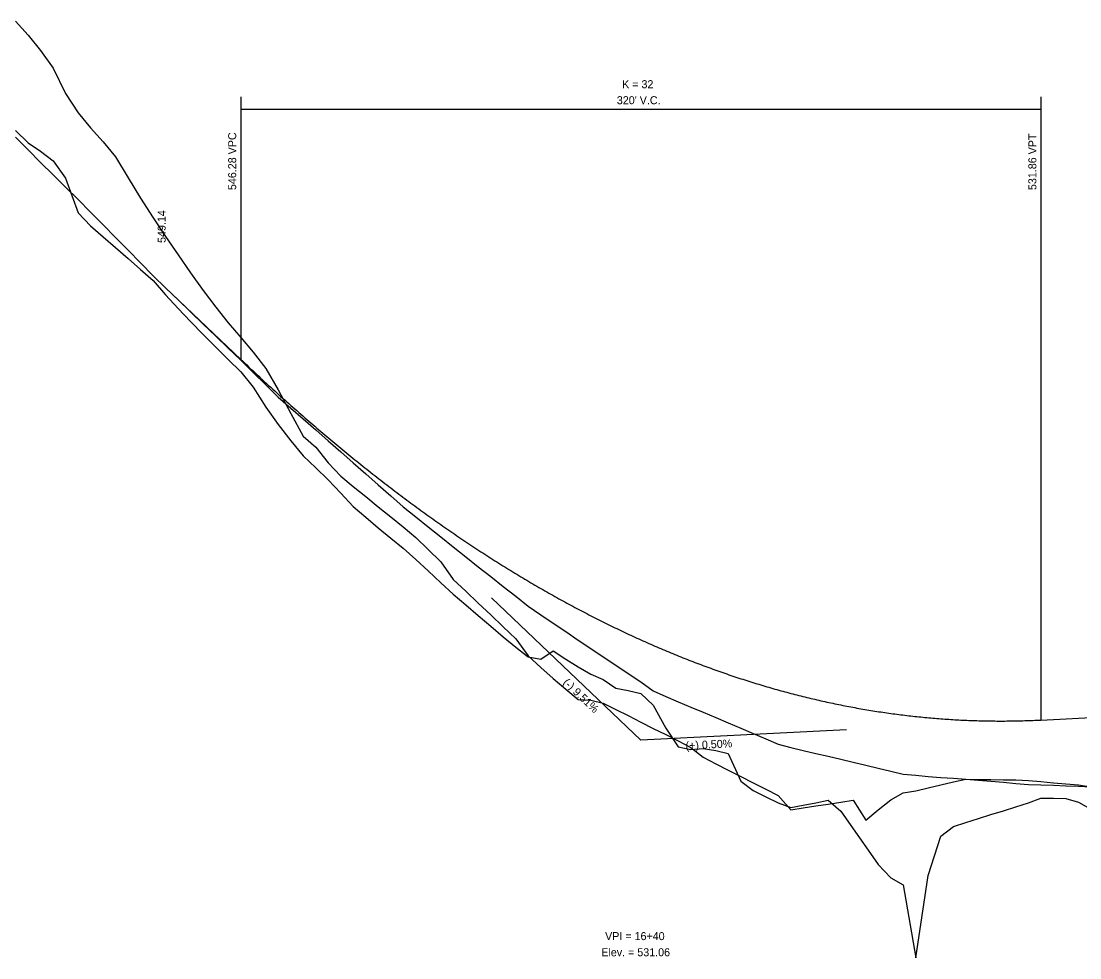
# Model space of a CAD drawing. Extents: x 1511486 to 1516886, y 901686 to 906985.
# Drawn here: x 1513466.9 to 1513890.3, y 905410 to 905784.5 of the extents above; entities that cross this region are included whole.
import ezdxf

# ---------------------------------------------------------------- set-up
doc = ezdxf.new("R2010")
doc.units = 0
for name, color, linetype in [('RD_DDB_GradeTX', 7, 'Continuous'), ('RD_DDB_Profile_EX', 7, 'Continuous'), ('RD_DDB_Profile_Lbl', 7, 'Continuous'), ('RD_DDB_Profile_PR', 7, 'Continuous'), ('RD_DDB_StripGrade', 7, 'Continuous'), ('RD_DDB_VCLbl', 7, 'Continuous'), ('RD_Sketch2', 7, 'Continuous')]:
    doc.layers.add(name, color=color, linetype=linetype)

msp = doc.modelspace()

# ---------------------------------------------------------------- linework, layer by layer
at = {"layer": 'RD_DDB_GradeTX'}
for p in [(1513654.99, 905553.85), (1513796.98, 905501.17)]:
    msp.add_line(p, (1513714.68, 905497.05), dxfattribs=at)
at = {"layer": 'RD_DDB_Profile_EX'}
for points in [[(1513464.68, 905738.06), (1513469.68, 905733.06), (1513474.68, 905727.99), (1513479.68, 905723.08), (1513484.68, 905718.14), (1513489.68, 905713.14), (1513494.68, 905708.06), (1513499.68, 905703.05), (1513504.68, 905698.01), (1513509.68, 905692.93), (1513514.68, 905687.83), (1513519.68, 905682.7), (1513524.68, 905677.81), (1513529.68, 905673.07), (1513534.68, 905668.31), (1513539.68, 905663.35), (1513544.68, 905658.55), (1513549.68, 905653.76), (1513554.68, 905648.92), (1513559.68, 905644.03), (1513564.68, 905639.1), (1513569.68, 905634.12), (1513574.68, 905629.7)], [(1513574.68, 905629.7), (1513579.68, 905625.42), (1513584.68, 905621.08), (1513589.68, 905616.68), (1513594.68, 905612.31), (1513599.68, 905607.93), (1513604.68, 905603.54), (1513609.68, 905599.15), (1513614.68, 905594.75), (1513619.68, 905590.35), (1513624.68, 905586.26), (1513629.68, 905582.27), (1513634.68, 905578.3), (1513639.68, 905574.3), (1513644.68, 905570.32), (1513649.68, 905566.35), (1513654.68, 905562.4), (1513659.68, 905558.46), (1513664.68, 905554.53), (1513669.68, 905550.61), (1513674.68, 905547.17), (1513679.68, 905543.78), (1513684.68, 905540.4), (1513689.68, 905537.03), (1513694.68, 905533.67), (1513699.68, 905530.31), (1513704.68, 905526.97), (1513709.68, 905523.64), (1513714.68, 905520.31), (1513719.68, 905516.76), (1513724.68, 905514.41), (1513729.68, 905512.27), (1513734.68, 905510.14), (1513739.68, 905508.14), (1513744.68, 905506.03), (1513749.68, 905503.92), (1513754.68, 905501.8), (1513759.68, 905499.68), (1513764.68, 905497.56), (1513769.68, 905495.45), (1513774.68, 905494.12), (1513779.68, 905492.93), (1513784.68, 905491.73), (1513789.68, 905490.54), (1513794.68, 905489.34), (1513799.68, 905488.15), (1513804.68, 905486.95), (1513809.68, 905485.75), (1513814.68, 905484.55), (1513819.68, 905483.36), (1513824.68, 905482.94), (1513829.68, 905482.52), (1513834.68, 905482.11), (1513839.68, 905481.82), (1513844.68, 905481.4), (1513849.68, 905480.98), (1513854.68, 905480.56), (1513859.68, 905480.14), (1513864.68, 905479.72), (1513869.68, 905479.3), (1513874.68, 905479.16), (1513879.68, 905478.97), (1513884.68, 905478.78), (1513889.68, 905478.58), (1513894.68, 905478.39)]]:
    msp.add_lwpolyline(points, dxfattribs=at)
at = {"layer": 'RD_DDB_Profile_PR'}
for p, q in [((1513524.68, 905677.81), (1513554.68, 905649.27)), ((1513874.68, 905505.05), (1514254.68, 905524.05))]:
    msp.add_line(p, q, dxfattribs=at)
msp.add_spline([(1513554.68, 905649.27), (1513561.08, 905643.25), (1513567.48, 905637.35), (1513573.88, 905631.58), (1513580.28, 905625.94), (1513586.68, 905620.43), (1513593.08, 905615.05), (1513599.48, 905609.79), (1513605.88, 905604.66), (1513612.28, 905599.66), (1513618.68, 905594.79), (1513625.08, 905590.05), (1513631.48, 905585.44), (1513637.88, 905580.95), (1513644.28, 905576.59), (1513650.68, 905572.36), (1513657.08, 905568.26), (1513663.48, 905564.28), (1513669.88, 905560.44), (1513676.28, 905556.72), (1513682.68, 905553.13), (1513689.08, 905549.67), (1513695.48, 905546.34), (1513701.88, 905543.13), (1513708.28, 905540.06), (1513714.68, 905537.11), (1513721.08, 905534.29), (1513727.48, 905531.6), (1513733.88, 905529.03), (1513740.28, 905526.6), (1513746.68, 905524.29), (1513753.08, 905522.11), (1513759.48, 905520.06), (1513765.88, 905518.14), (1513772.28, 905516.34), (1513778.68, 905514.67), (1513785.08, 905513.14), (1513791.48, 905511.73), (1513797.88, 905510.44), (1513804.28, 905509.29), (1513810.68, 905508.26), (1513817.08, 905507.37), (1513823.48, 905506.6), (1513829.88, 905505.96), (1513836.28, 905505.44), (1513842.68, 905505.06), (1513849.08, 905504.8), (1513855.48, 905504.67), (1513861.88, 905504.67), (1513868.28, 905504.8), (1513874.68, 905505.05)], degree=3, dxfattribs=at)
at = {"layer": 'RD_DDB_VCLbl'}
for p, q in [((1513554.68, 905754.27), (1513554.68, 905649.27)), ((1513874.68, 905754.27), (1513874.68, 905505.05)), ((1513554.68, 905749.27), (1513874.68, 905749.27))]:
    msp.add_line(p, q, dxfattribs=at)
at = {"layer": 'RD_Sketch2'}
for points in [[(1513464.68, 905784.48), (1513469.68, 905778.91), (1513474.68, 905772.7), (1513479.68, 905765.66), (1513484.68, 905755.57), (1513489.68, 905747.89), (1513494.68, 905741.9), (1513499.68, 905736.24), (1513504.68, 905730.24), (1513509.68, 905721.87), (1513514.68, 905713.74), (1513519.68, 905705.89), (1513524.68, 905698.35), (1513529.68, 905691.08), (1513534.68, 905683.8), (1513539.68, 905676.75), (1513544.68, 905670.13), (1513549.68, 905663.93), (1513554.68, 905657.99), (1513559.68, 905652.15), (1513564.68, 905645.56), (1513569.68, 905637.04), (1513574.68, 905627.57)], [(1513464.68, 905740.83), (1513469.68, 905735.83), (1513474.68, 905732.45), (1513479.68, 905728.66), (1513484.68, 905721.76), (1513489.68, 905707.89), (1513494.68, 905702.66), (1513499.68, 905698.31), (1513504.68, 905693.92), (1513509.68, 905689.54), (1513514.68, 905685.19), (1513519.68, 905680.78), (1513524.68, 905675.07), (1513529.68, 905669.61), (1513534.68, 905664.37), (1513539.68, 905659.22), (1513544.68, 905654.16), (1513549.68, 905649.18), (1513554.68, 905644.29), (1513559.68, 905638.1), (1513564.68, 905630.2), (1513569.68, 905623.15), (1513574.68, 905616.65)], [(1513574.68, 905627.57), (1513579.68, 905618.56), (1513584.68, 905614.14), (1513589.68, 905607.86), (1513594.68, 905602.58), (1513599.68, 905598.48), (1513604.68, 905594.41), (1513609.68, 905590.36), (1513614.68, 905586.33), (1513619.68, 905582.32), (1513624.68, 905578), (1513629.68, 905573.17), (1513634.68, 905568.29), (1513639.68, 905561.27), (1513644.68, 905556.56), (1513649.68, 905551.83), (1513654.68, 905547.06), (1513659.68, 905542.28), (1513664.68, 905537.46), (1513669.68, 905530.67), (1513674.68, 905526.01), (1513679.68, 905521.7), (1513684.68, 905517.33), (1513689.68, 905513.24), (1513694.68, 905513.02), (1513699.68, 905511.84), (1513704.68, 905509.32), (1513709.68, 905506.8), (1513714.68, 905504.26), (1513719.68, 905501.71), (1513724.68, 905499.21), (1513729.68, 905496.67), (1513734.68, 905494.1), (1513739.68, 905490.15), (1513744.68, 905487.58), (1513749.68, 905485.04), (1513754.68, 905482.49), (1513759.68, 905479.95), (1513764.68, 905477.4), (1513769.68, 905474.81), (1513774.68, 905469.11), (1513779.68, 905469.89), (1513784.68, 905470.68), (1513789.68, 905471.46), (1513794.68, 905472.24), (1513799.68, 905473.03), (1513804.68, 905465.05), (1513809.68, 905469.12), (1513814.68, 905473.19), (1513819.68, 905475.96), (1513824.68, 905476.7), (1513829.68, 905477.9), (1513834.68, 905479.11), (1513839.68, 905480.31), (1513844.68, 905481.41), (1513849.68, 905481.33), (1513854.68, 905481.26), (1513859.68, 905481.18), (1513864.68, 905481.1), (1513869.68, 905480.86), (1513874.68, 905480.41), (1513879.68, 905479.96), (1513884.68, 905479.5), (1513889.68, 905479.13), (1513894.68, 905478.38)], [(1513574.68, 905616.65), (1513579.68, 905610.72), (1513584.68, 905605.93), (1513589.68, 905601.13), (1513594.68, 905595.72), (1513599.68, 905590.46), (1513604.68, 905586.15), (1513609.68, 905581.94), (1513614.68, 905577.83), (1513619.68, 905573.81), (1513624.68, 905569.3), (1513629.68, 905564.68), (1513634.68, 905559.97), (1513639.68, 905555.37), (1513644.68, 905551.07), (1513649.68, 905546.9), (1513654.68, 905542.55), (1513659.68, 905538.33), (1513664.68, 905534.23), (1513669.68, 905530.27), (1513674.68, 905529.39), (1513679.68, 905532.74), (1513684.68, 905529.34), (1513689.68, 905526.33), (1513694.68, 905523.36), (1513699.68, 905521.2), (1513704.68, 905517.78), (1513709.68, 905516.92), (1513714.68, 905515.71), (1513719.68, 905511.03), (1513724.68, 905501.74), (1513729.68, 905494.39), (1513734.68, 905493.31), (1513739.68, 905493.73), (1513744.68, 905492.86), (1513749.68, 905491.62), (1513754.68, 905480.65), (1513759.68, 905476.87), (1513764.68, 905474.36), (1513769.68, 905472), (1513774.68, 905470.02), (1513779.68, 905470.99), (1513784.68, 905471.97), (1513789.68, 905472.94), (1513794.68, 905468.61), (1513799.68, 905461.48), (1513804.68, 905454.36), (1513809.68, 905447.23), (1513814.68, 905441.95), (1513819.68, 905439.21), (1513824.68, 905409.97), (1513829.68, 905442.89), (1513834.68, 905458.62), (1513839.68, 905462.43), (1513844.68, 905464.02), (1513849.68, 905465.61), (1513854.68, 905467.21), (1513859.68, 905468.8), (1513864.68, 905470.39), (1513869.68, 905471.98), (1513874.68, 905473.75), (1513879.68, 905473.79), (1513884.68, 905473.7), (1513889.68, 905472.24), (1513894.68, 905469.44)]]:
    msp.add_lwpolyline(points, dxfattribs=at)

# ---------------------------------------------------------------- texts
at = {"layer": 'RD_DDB_GradeTX'}
for s, rotation, p in [('(-) 9.51%', 316.4283, (1513683.31, 905519.71)), ('(+) 0.50%', 2.8624, (1513732.67, 905493.22))]:
    msp.add_text(s, height=3.2, rotation=rotation, dxfattribs=at).set_placement(p)
at = {"layer": 'RD_DDB_Profile_Lbl'}
msp.add_text('549.14', height=3.2, rotation=90, dxfattribs=at).set_placement((1513524.68, 905695.81))
for s, p in [('VPI = 16+40', (1513700.43, 905417.05)), ('Elev. = 531.06', (1513698.91, 905410.59))]:
    msp.add_text(s, height=3.2, dxfattribs=at).set_placement(p)
at = {"layer": 'RD_DDB_StripGrade'}
for s, p in [('546.28 VPC', (1513552.89, 905716.95)), ('531.86 VPT', (1513872.89, 905716.95))]:
    msp.add_text(s, height=3.2, rotation=90, dxfattribs=at).set_placement(p)
at = {"layer": 'RD_DDB_VCLbl'}
for s, p in [('K = 32', (1513707.24, 905757.67)), ("320' V.C.", (1513705.12, 905751.27))]:
    msp.add_text(s, height=3.2, dxfattribs=at).set_placement(p)

doc.saveas('drawing.dxf')
